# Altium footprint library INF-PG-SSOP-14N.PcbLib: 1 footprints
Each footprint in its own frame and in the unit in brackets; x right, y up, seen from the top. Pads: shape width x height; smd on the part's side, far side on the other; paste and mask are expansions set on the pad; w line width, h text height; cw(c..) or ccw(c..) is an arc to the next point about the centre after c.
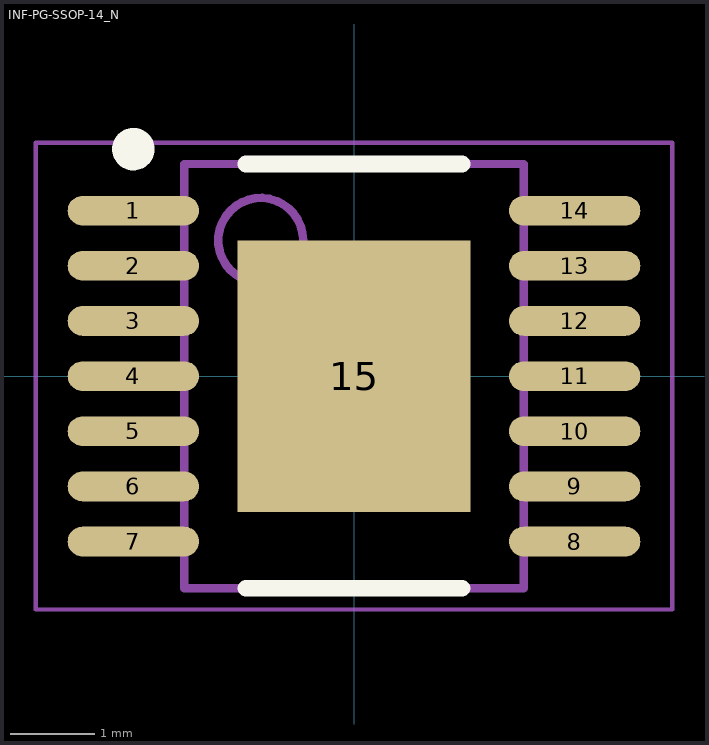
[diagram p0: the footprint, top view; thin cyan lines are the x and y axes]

## INF-PG-SSOP-14_N [mm] "SOP, 14-Leads, Body 4.9x3.9mm, Pitch 0.65mm, Thermal Pad 3.2x2.75mm, IPC Medium Density"
height 1.7
pads (15):
  oval 1.55x0.35 smd: 1(-2.6,1.95) 2(-2.6,1.3) 3(-2.6,0.65) 4(-2.6,0) 5(-2.6,-0.65) 6(-2.6,-1.3) 7(-2.6,-1.95) 8(2.6,-1.95) 9(2.6,-1.3) 10(2.6,-0.65) 11(2.6,0) 12(2.6,0.65) 13(2.6,1.3) 14(2.6,1.95)
  rect 2.75x3.2 smd: 15(0,0)
Top Overlay:
  circle w0.25: c-2.6,2.675 r0.125
  lines w0.2: -1.275,-2.5 1.275,-2.5 ; -1.275,2.5 1.275,2.5
Mechanical 13:
  circle w0.1: c-1.1,1.6 r0.5
  lines w0.1: -2,-2.5 2,-2.5 2,2.5 -2,2.5 -2,-2.5
Mechanical 15:
  lines w0.05: -3.75,-2.75 3.75,-2.75 3.75,2.75 -3.75,2.75 -3.75,-2.75
  lines w0.1: -0.5,0 0.5,0 ; 0,-0.5 0,0.5
3D body: height 1.7, standoff 0, extent -2,-2.5 2,2.5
